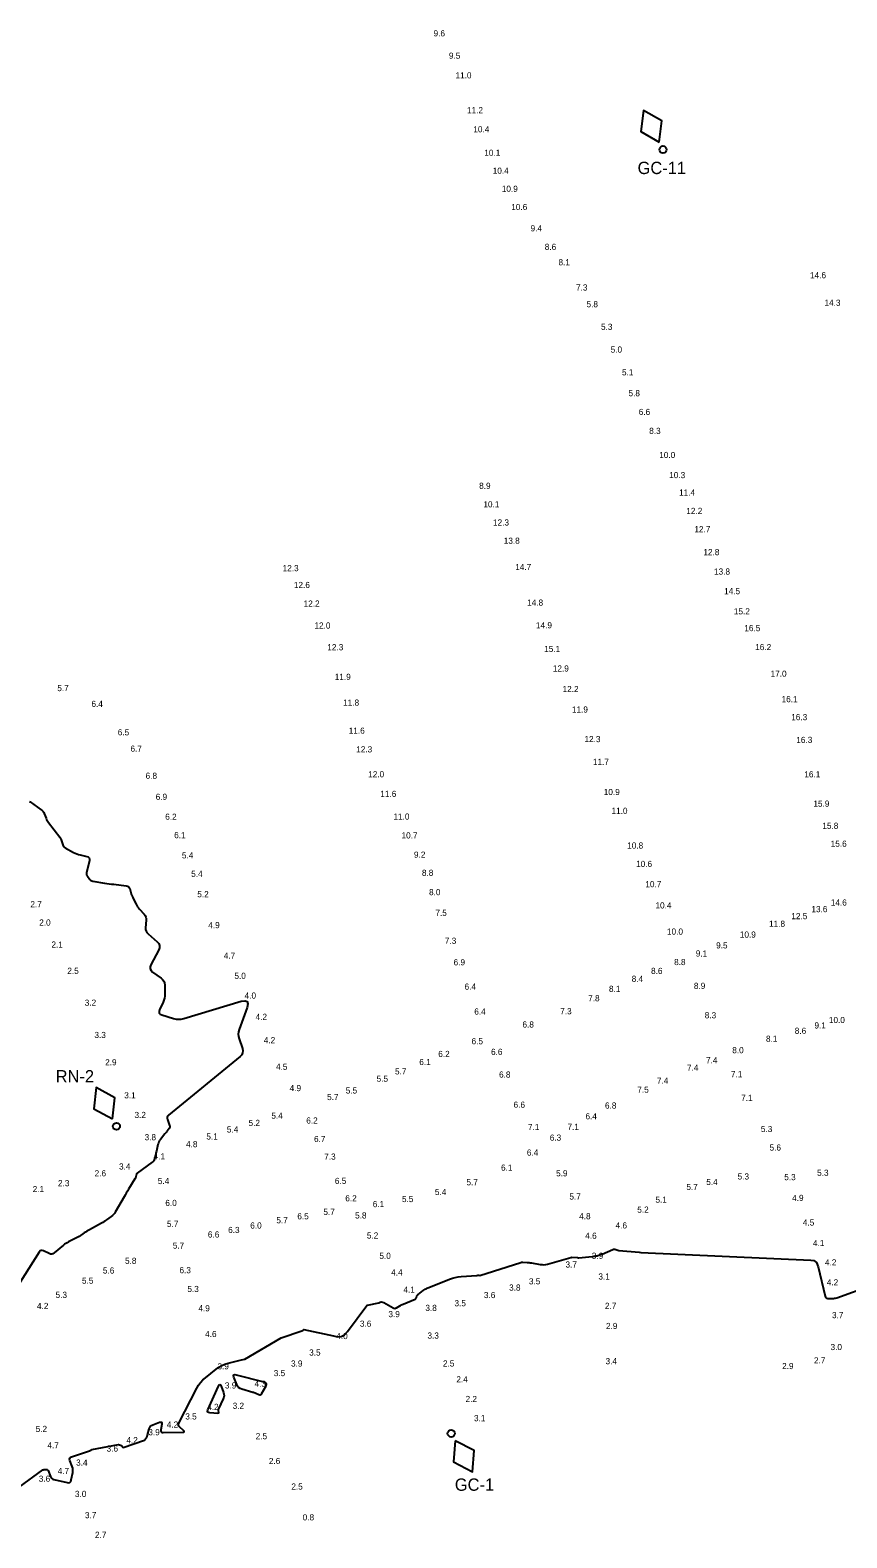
# Model space of a CAD drawing. Extents: x 837127 to 848654, y 3074248 to 3079868.
# Drawn here: x 847833 to 848248, y 3078565 to 3079331 of the extents above; entities that cross this region are included whole.
import ezdxf

# ---------------------------------------------------------------- set-up
doc = ezdxf.new("R2010")
doc.units = 0
for name, color, linetype in [('V-CHAN-NAID', 7, 'Continuous'), ('V-HYDS-MAJR', 7, 'Continuous'), ('V-HYDS-SOUN', 7, 'Continuous')]:
    doc.layers.add(name, color=color, linetype=linetype)

msp = doc.modelspace()

# ---------------------------------------------------------------- linework, layer by layer
at = {"layer": 'V-CHAN-NAID'}
for points in [[(848152.71, 3079274.19), (848154.07, 3079284.92), (848144.68, 3079290.3), (848143.32, 3079279.57)], [(847874.79, 3078777.98), (847875.89, 3078788.74), (847866.38, 3078793.9), (847865.28, 3078783.14)], [(848048.96, 3078614.55), (848048.07, 3078603.77), (848057.68, 3078598.8), (848058.57, 3078609.58)]]:
    msp.add_lwpolyline(points, close=True, dxfattribs=at)
for centre in [(848154.58, 3079270.43), (847876.75, 3078774.27), (848046.92, 3078618.22)]:
    msp.add_circle(centre, 1.8, dxfattribs=at)
at = {"layer": 'V-HYDS-MAJR'}
for points in [[(847832.64, 3078939.29), (847832.92, 3078939.06), (847838.55, 3078935.01), (847839.03, 3078934.61), (847839.44, 3078934.16), (847839.79, 3078933.65), (847840.06, 3078933.09), (847841, 3078930.73), (847841.26, 3078930.15), (847841.55, 3078929.59), (847841.88, 3078929.05), (847842.25, 3078928.54), (847847.95, 3078921.07), (847848.24, 3078920.65), (847848.5, 3078920.2), (847848.71, 3078919.73), (847848.88, 3078919.24), (847849.47, 3078917.23), (847849.65, 3078916.76), (847849.92, 3078916.35), (847850.26, 3078916), (847850.68, 3078915.72), (847855, 3078913.35), (847855.78, 3078912.96), (847856.59, 3078912.62), (847857.41, 3078912.34), (847858.26, 3078912.12), (847861.69, 3078911.33), (847862.41, 3078911.06), (847862.88, 3078910.61), (847863.08, 3078910), (847863.02, 3078909.23), (847861.62, 3078902.96), (847861.57, 3078902.5), (847861.61, 3078902.06), (847861.76, 3078901.64), (847862, 3078901.24), (847863.19, 3078899.7), (847863.51, 3078899.35), (847863.88, 3078899.08), (847864.29, 3078898.89), (847864.75, 3078898.77), (847870.73, 3078897.83), (847871.88, 3078897.65), (847873.04, 3078897.49), (847874.2, 3078897.33), (847875.36, 3078897.19), (847881.76, 3078896.44), (847882.37, 3078896.29), (847882.87, 3078896), (847883.25, 3078895.56), (847883.51, 3078894.99), (847884.31, 3078892.4), (847884.52, 3078891.76), (847884.76, 3078891.13), (847885.03, 3078890.51), (847885.32, 3078889.89), (847886.75, 3078887.05), (847887.11, 3078886.39), (847887.52, 3078885.76), (847887.96, 3078885.16), (847888.45, 3078884.58), (847890.84, 3078881.93), (847891.33, 3078881.28), (847891.66, 3078880.57), (847891.83, 3078879.81), (847891.85, 3078878.99), (847891.57, 3078875.14), (847891.6, 3078874.26), (847891.82, 3078873.45), (847892.23, 3078872.72), (847892.83, 3078872.07), (847897.5, 3078867.97), (847898.31, 3078867.04), (847898.7, 3078866.04), (847898.69, 3078864.96), (847898.27, 3078863.81), (847894.29, 3078856.24), (847893.91, 3078855.18), (847893.93, 3078854.22), (847894.35, 3078853.36), (847895.16, 3078852.58), (847899.44, 3078849.55), (847900.25, 3078848.83), (847900.82, 3078848.01), (847901.18, 3078847.06), (847901.3, 3078845.99), (847901.36, 3078841.38), (847901.31, 3078840.32), (847901.15, 3078839.29), (847900.88, 3078838.28), (847900.49, 3078837.29), (847898.7, 3078833.4), (847898.43, 3078832.51), (847898.54, 3078831.79), (847899.01, 3078831.23), (847899.85, 3078830.83), (847905.73, 3078829.03), (847907.06, 3078828.73), (847908.38, 3078828.63), (847909.7, 3078828.72), (847911.03, 3078829.02), (847940.24, 3078837.74), (847942.15, 3078838.05), (847943.28, 3078837.64), (847943.62, 3078836.49), (847943.19, 3078834.6), (847939.12, 3078823.47), (847938.79, 3078822.27), (847938.67, 3078821.06), (847938.77, 3078819.85), (847939.08, 3078818.64), (847940.78, 3078813.78), (847941.03, 3078812.62), (847940.92, 3078811.56), (847940.46, 3078810.59), (847939.64, 3078809.73), (847903.22, 3078779.91), (847902.78, 3078779.45), (847902.54, 3078778.93), (847902.49, 3078778.36), (847902.64, 3078777.74), (847903.81, 3078774.68), (847903.91, 3078774.28), (847903.91, 3078773.89), (847903.8, 3078773.51), (847903.59, 3078773.15), (847902.52, 3078771.74), (847902.25, 3078771.39), (847901.97, 3078771.04), (847901.7, 3078770.69), (847901.42, 3078770.35), (847899.16, 3078767.6), (847898.73, 3078767.01), (847898.38, 3078766.39), (847898.1, 3078765.72), (847897.89, 3078765.02), (847897.1, 3078761.66), (847896.99, 3078761.16), (847896.86, 3078760.66), (847896.74, 3078760.16), (847896.61, 3078759.66), (847896.09, 3078757.67), (847895.92, 3078757.19), (847895.69, 3078756.77), (847895.38, 3078756.39), (847895, 3078756.06), (847887.35, 3078750.39), (847887.16, 3078750.22), (847887, 3078750.03), (847886.89, 3078749.81), (847886.81, 3078749.56), (847886.56, 3078748.54), (847886.49, 3078748.28), (847886.4, 3078748.04), (847886.29, 3078747.8), (847886.17, 3078747.57), (847882.94, 3078742.24), (847882.36, 3078741.28), (847881.78, 3078740.31), (847881.21, 3078739.34), (847880.63, 3078738.37), (847876.12, 3078730.66), (847875.71, 3078730.04), (847875.25, 3078729.47), (847874.74, 3078728.94), (847874.16, 3078728.47), (847871.76, 3078726.68), (847871.16, 3078726.24), (847870.54, 3078725.83), (847869.9, 3078725.43), (847869.25, 3078725.06), (847863.12, 3078721.72), (847862.44, 3078721.33), (847861.76, 3078720.94), (847861.09, 3078720.52), (847860.42, 3078720.1), (847857.74, 3078718.35), (847857.1, 3078717.94), (847856.44, 3078717.55), (847855.78, 3078717.19), (847855.1, 3078716.84), (847852.36, 3078715.49), (847851.69, 3078715.13), (847851.05, 3078714.74), (847850.42, 3078714.31), (847849.83, 3078713.84), (847845.1, 3078709.9), (847844.49, 3078709.5), (847843.86, 3078709.32), (847843.2, 3078709.35), (847842.52, 3078709.6), (847839.74, 3078711), (847839.08, 3078711.22), (847838.49, 3078711.19), (847837.97, 3078710.91), (847837.52, 3078710.38), (847827.04, 3078693.68)], [(847827.34, 3078590.93), (847839.42, 3078599.71), (847839.63, 3078599.83), (847839.85, 3078599.92), (847840.08, 3078599.96), (847840.33, 3078599.96), (847841.32, 3078599.89), (847841.55, 3078599.84), (847841.74, 3078599.74), (847841.9, 3078599.59), (847842.01, 3078599.38), (847843.25, 3078596.3), (847843.54, 3078595.76), (847843.92, 3078595.34), (847844.4, 3078595.03), (847844.97, 3078594.82), (847851.69, 3078593.24), (847852.48, 3078593.17), (847853.1, 3078593.37), (847853.54, 3078593.85), (847853.81, 3078594.6), (847854.56, 3078598.32), (847854.67, 3078599.11), (847854.65, 3078599.89), (847854.52, 3078600.65), (847854.28, 3078601.41), (847853.07, 3078604.41), (847852.9, 3078605.1), (847853, 3078605.66), (847853.37, 3078606.1), (847854, 3078606.42), (847863.12, 3078609.39), (847863.43, 3078609.51), (847863.72, 3078609.67), (847863.99, 3078609.86), (847864.24, 3078610.08), (847877.79, 3078612.58), (847879.28, 3078612.03), (847880.17, 3078611.15), (847891.03, 3078614.84), (847891.56, 3078615.42), (847892, 3078616.05), (847892.34, 3078616.74), (847892.59, 3078617.49), (847893.4, 3078620.57), (847893.67, 3078621.28), (847894.08, 3078621.87), (847894.62, 3078622.33), (847895.3, 3078622.67), (847898.65, 3078623.91), (847899.24, 3078624.04), (847899.62, 3078623.93), (847899.81, 3078623.57), (847899.78, 3078622.97), (847899.28, 3078620.05), (847899.27, 3078619.42), (847899.47, 3078618.97), (847899.88, 3078618.7), (847900.51, 3078618.63), (847910.48, 3078618.84), (847910.98, 3078618.91), (847911.21, 3078619.08), (847911.15, 3078619.36), (847910.82, 3078619.74), (847908.92, 3078621.49), (847908.54, 3078621.95), (847908.36, 3078622.43), (847908.37, 3078622.96), (847908.56, 3078623.51), (847917.69, 3078641.25), (847918.56, 3078642.74), (847919.57, 3078644.12), (847920.72, 3078645.39), (847922.01, 3078646.55), (847927.44, 3078650.94), (847928.85, 3078651.95), (847930.33, 3078652.78), (847931.91, 3078653.45), (847933.56, 3078653.94), (847940.4, 3078655.55), (847942.11, 3078655.88), (847960.51, 3078666.83), (847970.92, 3078670.42), (847971.29, 3078670.57), (847971.63, 3078670.77), (847971.95, 3078671), (847987.04, 3078667.88), (847989.13, 3078667.36), (847991.02, 3078667.53), (847992.72, 3078668.39), (847994.22, 3078669.94), (848003.98, 3078683.15), (848004.16, 3078683.34), (848004.36, 3078683.43), (848010.1, 3078684.65), (848010.74, 3078684.95), (848011.39, 3078685.06), (848012.03, 3078684.98), (848012.68, 3078684.7), (848017.37, 3078682.02), (848017.8, 3078681.84), (848018.22, 3078681.78), (848018.65, 3078681.84), (848019.07, 3078682.03), (848020.76, 3078683.01), (848021.19, 3078683.25), (848021.62, 3078683.48), (848022.07, 3078683.69), (848022.51, 3078683.88), (848028.63, 3078686.43), (848028.84, 3078686.54), (848029.01, 3078686.69), (848029.14, 3078686.88), (848029.23, 3078687.11), (848029.51, 3078688.08), (848029.6, 3078688.31), (848029.72, 3078688.52), (848029.87, 3078688.7), (848030.05, 3078688.86), (848032.64, 3078690.78), (848033.15, 3078691.13), (848033.68, 3078691.45), (848034.22, 3078691.73), (848034.79, 3078691.98), (848046.12, 3078696.56), (848047.53, 3078697.07), (848048.97, 3078697.47), (848050.43, 3078697.75), (848051.92, 3078697.92), (848059.95, 3078698.53), (848060.44, 3078698.56), (848060.92, 3078698.55), (848061.41, 3078698.5), (848082.29, 3078705.13), (848082.74, 3078705.29), (848083.26, 3078705.31), (848085.48, 3078705.15), (848086.03, 3078705.1), (848086.58, 3078705.04), (848087.13, 3078704.96), (848087.68, 3078704.87), (848092.18, 3078704.08), (848093.11, 3078703.97), (848094.03, 3078703.96), (848094.95, 3078704.06), (848095.87, 3078704.26), (848107.72, 3078707.53), (848107.97, 3078707.62), (848108.21, 3078707.74), (848111.12, 3078707.63), (848111.34, 3078707.5), (848111.59, 3078707.44), (848111.87, 3078707.43), (848120.28, 3078708.33), (848120.57, 3078708.37), (848120.85, 3078708.43), (848121.13, 3078708.5), (848121.41, 3078708.58), (848122.51, 3078708.96), (848122.79, 3078709.05), (848123.06, 3078709.15), (848123.33, 3078709.26), (848123.6, 3078709.37), (848129.02, 3078711.66), (848129.4, 3078711.78), (848129.79, 3078711.84), (848130.18, 3078711.82), (848130.58, 3078711.73), (848132.16, 3078711.22), (848142.5, 3078710.32), (848143.24, 3078710.12), (848229.64, 3078706.17), (848231.31, 3078706.1), (848232.57, 3078704.99), (848233.42, 3078702.85), (848236.99, 3078687.99), (848237.17, 3078687.5), (848237.47, 3078687.15), (848237.88, 3078686.93), (848238.39, 3078686.85), (848240.67, 3078686.8), (848241.23, 3078686.81), (848241.79, 3078686.87), (848242.34, 3078686.99), (848242.88, 3078687.16), (848260.67, 3078693.63)]]:
    msp.add_lwpolyline(points, dxfattribs=at)
for points in [[(847929.29, 3078643.11), (847929.62, 3078642.9), (847929.94, 3078642.29), (847931.2, 3078639.05), (847931.42, 3078638.25), (847931.48, 3078637.45), (847931.36, 3078636.65), (847931.07, 3078635.87), (847928.6, 3078630.7), (847928.52, 3078630.48), (847928.47, 3078630.26), (847928.46, 3078630.04), (847928.48, 3078629.81), (847928.64, 3078628.88), (847928.64, 3078628.67), (847928.58, 3078628.53), (847928.44, 3078628.45), (847928.24, 3078628.44), (847924.16, 3078628.69), (847923.53, 3078628.81), (847923.17, 3078629.1), (847923.08, 3078629.56), (847923.25, 3078630.17), (847928.61, 3078642.32), (847928.96, 3078642.92)], [(847949.89, 3078637.75), (847949.57, 3078637.72), (847949.2, 3078637.83), (847947.63, 3078638.52), (847947.24, 3078638.69), (847946.84, 3078638.84), (847946.43, 3078638.98), (847946.02, 3078639.11), (847940.47, 3078640.73), (847939.6, 3078641.09), (847938.88, 3078641.6), (847938.31, 3078642.27), (847937.89, 3078643.1), (847936.47, 3078646.75), (847936.28, 3078647.52), (847936.41, 3078647.99), (847936.87, 3078648.18), (847937.66, 3078648.08), (847951.77, 3078644.42), (847952.49, 3078644.11), (847952.88, 3078643.66), (847952.94, 3078643.07), (847952.66, 3078642.33), (847950.4, 3078638.23), (847950.17, 3078637.92)]]:
    msp.add_lwpolyline(points, close=True, dxfattribs=at)

# ---------------------------------------------------------------- texts
at = {"layer": 'V-CHAN-NAID'}
for s, p in [('GC-11', (848141.67, 3079257.96)), ('RN-2', (847845.88, 3078796.54)), ('GC-1', (848048.76, 3078589.11))]:
    msp.add_text(s, height=6.25, dxfattribs=at).set_placement(p)
at = {"layer": 'V-HYDS-SOUN'}
for s, p in [('9.6', (848037.95, 3079327.89)), ('9.5', (848045.77, 3079316.53)), ('11.0 ', (848049.11, 3079306.55)), ('11.2 ', (848054.96, 3079288.87)), ('10.4 ', (848058.19, 3079279.16)), ('10.1 ', (848063.74, 3079267.23)), ('10.4 ', (848068.03, 3079258.1)), ('10.9 ', (848072.64, 3079248.91)), ('10.6 ', (848077.45, 3079239.66)), ('9.4', (848087.26, 3079228.84)), ('8.6', (848094.48, 3079219.42)), ('8.1', (848101.46, 3079211.61)), ('14.6 ', (848229.31, 3079205.03)), ('7.3', (848110.38, 3079198.79)), ('5.8', (848115.71, 3079190.3)), ('14.3 ', (848236.66, 3079191.03)), ('5.3', (848123.07, 3079178.81)), ('5.0', (848127.96, 3079167.27)), ('5.1', (848133.73, 3079155.71)), ('5.8', (848137.05, 3079145.11)), ('6.6', (848142.26, 3079135.57)), ('8.3', (848147.57, 3079125.96)), ('10.0 ', (848152.66, 3079113.7)), ('8.9', (848061.14, 3079098.06)), ('10.3 ', (848157.73, 3079103.49)), ('11.4 ', (848162.74, 3079094.65)), ('10.1 ', (848063.29, 3079088.64)), ('12.2 ', (848166.43, 3079085.29)), ('12.3 ', (848068.16, 3079079.42)), ('12.7 ', (848170.53, 3079076.01)), ('13.8 ', (848073.63, 3079070.15)), ('12.8 ', (848175.12, 3079064.36)), ('12.3 ', (847961.24, 3079056.24)), ('14.7 ', (848079.48, 3079056.79)), ('13.8 ', (848180.51, 3079054.5)), ('12.6 ', (847966.97, 3079047.67)), ('14.5 ', (848185.63, 3079044.54)), ('12.2 ', (847971.91, 3079038.22)), ('14.8 ', (848085.51, 3079038.72)), ('15.2 ', (848190.59, 3079034.28)), ('12.0 ', (847977.41, 3079027.08)), ('14.9 ', (848090.01, 3079027.21)), ('16.5 ', (848195.92, 3079025.76)), ('12.3 ', (847983.95, 3079016.08)), ('15.1 ', (848094.16, 3079015.18)), ('16.2 ', (848201.44, 3079016.13)), ('11.9 ', (847987.73, 3079001)), ('12.9 ', (848098.58, 3079005.25)), ('17.0 ', (848209.27, 3079002.6)), ('5.7', (847846.72, 3078995.3)), ('12.2 ', (848103.53, 3078994.82)), ('6.4', (847864.06, 3078987.29)), ('11.8 ', (847991.98, 3078987.92)), ('11.9 ', (848108.29, 3078984.4)), ('16.1 ', (848214.86, 3078989.68)), ('16.3 ', (848219.75, 3078980.55)), ('6.5', (847877.44, 3078972.84)), ('11.6 ', (847994.84, 3078973.66)), ('12.3 ', (848114.66, 3078969.39)), ('16.3 ', (848222.34, 3078968.96)), ('6.7', (847883.89, 3078964.53)), ('12.3 ', (847998.63, 3078964.17)), ('11.7 ', (848118.95, 3078957.8)), ('6.8', (847891.6, 3078950.76)), ('12.0 ', (848004.72, 3078951.51)), ('16.1 ', (848226.42, 3078951.51)), ('6.9', (847896.71, 3078940.07)), ('11.6 ', (848010.89, 3078941.57)), ('10.9 ', (848124.47, 3078942.5)), ('15.9 ', (848231.02, 3078936.6)), ('6.2', (847901.56, 3078929.94)), ('11.0 ', (848017.57, 3078930.02)), ('11.0 ', (848128.41, 3078932.97)), ('15.8 ', (848235.58, 3078925.35)), ('6.1', (847906.11, 3078920.6)), ('10.7 ', (848021.67, 3078920.45)), ('10.8 ', (848136.37, 3078915.32)), ('15.6 ', (848239.81, 3078916.25)), ('5.4', (847910.04, 3078910.34)), ('9.2', (848028, 3078910.67)), ('10.6 ', (848140.91, 3078905.98)), ('5.4', (847914.77, 3078900.96)), ('8.8', (848032.05, 3078901.46)), ('5.2', (847917.86, 3078890.58)), ('8.0', (848035.67, 3078891.65)), ('10.7 ', (848145.62, 3078895.72)), ('2.7', (847833.03, 3078885.51)), ('10.4 ', (848150.76, 3078884.91)), ('13.6 ', (848230.02, 3078883.02)), ('14.6 ', (848239.87, 3078886.37)), ('2.0', (847837.51, 3078876.2)), ('7.5', (848038.89, 3078881.11)), ('11.8 ', (848208.48, 3078875.58)), ('12.5 ', (848219.81, 3078879.47)), ('4.9', (847923.44, 3078874.89)), ('10.0 ', (848156.61, 3078871.61)), ('10.9 ', (848193.63, 3078870.09)), ('2.1', (847843.73, 3078865)), ('7.3', (848043.69, 3078866.95)), ('9.1', (848171.25, 3078860.48)), ('9.5', (848181.58, 3078864.6)), ('4.7', (847931.34, 3078859.4)), ('6.9', (848048.14, 3078856.02)), ('8.8', (848160.23, 3078856.14)), ('2.5', (847851.81, 3078851.69)), ('5.0', (847936.73, 3078849.14)), ('8.4', (848138.68, 3078847.62)), ('8.6', (848148.52, 3078851.64)), ('4.0', (847941.91, 3078839.11)), ('6.4', (848053.72, 3078843.67)), ('7.8', (848116.55, 3078837.73)), ('8.1', (848127.11, 3078842.52)), ('8.9', (848170.28, 3078844.02)), ('3.2', (847860.65, 3078835.49)), ('6.4', (848058.66, 3078831)), ('7.3', (848102.34, 3078831.15)), ('4.2', (847947.51, 3078828.31)), ('6.8', (848083.14, 3078824.42)), ('8.3', (848175.8, 3078829.1)), ('9.1', (848231.56, 3078823.94)), ('10.0 ', (848238.9, 3078826.69)), ('3.3', (847865.57, 3078819.08)), ('4.2', (847951.66, 3078816.45)), ('6.5', (848057.28, 3078815.93)), ('8.1', (848206.92, 3078817.18)), ('8.6', (848221.56, 3078821.21)), ('6.2', (848040.35, 3078809.44)), ('6.6', (848067.18, 3078810.52)), ('8.0', (848189.77, 3078811.37)), ('2.9', (847871.03, 3078805.22)), ('4.5', (847957.86, 3078802.94)), ('5.7', (848018.35, 3078800.59)), ('6.1', (848030.71, 3078805.35)), ('6.8', (848071.25, 3078798.97)), ('7.4', (848166.77, 3078802.47)), ('7.4', (848176.45, 3078806.29)), ('7.1', (848189.1, 3078799.21)), ('4.9', (847964.8, 3078792.11)), ('5.5', (848009, 3078796.89)), ('7.5', (848141.53, 3078791.3)), ('7.4', (848151.49, 3078795.85)), ('3.1', (847880.73, 3078788.44)), ('5.7', (847983.84, 3078787.56)), ('5.5', (847993.31, 3078790.91)), ('6.6', (848078.63, 3078783.67)), ('7.1', (848194.3, 3078787.16)), ('3.2', (847885.95, 3078778.45)), ('5.4', (847955.51, 3078778.1)), ('6.4', (848115.16, 3078777.79)), ('6.8', (848125.09, 3078783.25)), ('5.4', (847932.89, 3078771.1)), ('5.2', (847943.92, 3078774.41)), ('6.2', (847973.26, 3078775.64)), ('7.1', (848085.96, 3078772.32)), ('7.1', (848106.04, 3078772.42)), ('5.3', (848204.33, 3078771.32)), ('3.8', (847891.07, 3078767.17)), ('4.8', (847912.15, 3078763.62)), ('5.1', (847922.47, 3078767.54)), ('6.7', (847977.2, 3078766.23)), ('6.3', (848097.03, 3078766.94)), ('5.6', (848208.74, 3078761.9)), ('4.1', (847895.67, 3078757.4)), ('7.3', (847982.38, 3078757.3)), ('6.4', (848085.39, 3078759.37)), ('2.6', (847865.67, 3078748.82)), ('3.4', (847878.08, 3078752.3)), ('6.1', (848072.26, 3078751.7)), ('5.9', (848100.25, 3078748.82)), ('5.3', (848192.5, 3078747.23)), ('5.3', (848216.21, 3078746.88)), ('5.3', (848232.93, 3078749.11)), ('2.1', (847834.19, 3078740.8)), ('2.3', (847847.05, 3078743.82)), ('5.4', (847897.81, 3078744.89)), ('6.5', (847987.8, 3078744.96)), ('5.4', (848038.63, 3078739.31)), ('5.7', (848054.68, 3078744.28)), ('5.7', (848166.47, 3078741.88)), ('5.4', (848176.58, 3078744.43)), ('6.0', (847901.61, 3078733.77)), ('6.2', (847993.09, 3078736.12)), ('6.1', (848007.06, 3078733.18)), ('5.5', (848021.9, 3078735.74)), ('5.7', (848107, 3078737.04)), ('5.2', (848141.49, 3078730.37)), ('5.1', (848150.74, 3078735.43)), ('4.9', (848220.23, 3078736.31)), ('5.7', (847902.43, 3078723.11)), ('6.0', (847944.78, 3078722.31)), ('5.7', (847958.06, 3078724.98)), ('6.5', (847968.71, 3078726.98)), ('5.7', (847981.95, 3078729.21)), ('5.8', (847998.07, 3078727.43)), ('4.8', (848111.97, 3078727.03)), ('4.6', (848130.47, 3078722.36)), ('4.5', (848225.65, 3078723.84)), ('6.6', (847923.25, 3078717.75)), ('6.3', (847933.55, 3078720.03)), ('5.2', (848004.07, 3078717.23)), ('4.6', (848115.04, 3078717.12)), ('5.7', (847905.4, 3078712.1)), ('5.0', (848010.42, 3078706.9)), ('3.9', (848118.4, 3078706.94)), ('4.1', (848230.79, 3078713.38)), ('5.6', (847869.88, 3078699.45)), ('5.8', (847881.12, 3078704.36)), ('6.3', (847908.81, 3078699.62)), ('3.7', (848105.02, 3078702.5)), ('4.2', (848236.9, 3078703.55)), ('5.5', (847859.24, 3078694.3)), ('4.4', (848016.39, 3078698.46)), ('3.5', (848086.42, 3078693.96)), ('3.1', (848121.73, 3078696.41)), ('4.2', (848237.82, 3078693.42)), ('5.3', (847845.83, 3078687.07)), ('5.3', (847912.82, 3078690.05)), ('4.1', (848022.64, 3078689.71)), ('3.6', (848063.53, 3078686.98)), ('3.8', (848076.36, 3078690.77)), ('4.2', (847836.37, 3078681.43)), ('4.9', (847918.42, 3078680.27)), ('3.9', (848015.01, 3078677.3)), ('3.8', (848033.8, 3078680.44)), ('3.5', (848048.59, 3078682.83)), ('2.7', (848125.07, 3078681.5)), ('3.7', (848240.48, 3078676.79)), ('3.6', (848000.51, 3078672.43)), ('2.9', (848125.59, 3078671.26)), ('4.6', (847921.85, 3078667.18)), ('4.0', (847988.49, 3078666.15)), ('3.3', (848034.86, 3078666.39)), ('3.5', (847974.73, 3078657.78)), ('3.4', (848125.37, 3078653.39)), ('2.7', (848231.32, 3078653.81)), ('3.0', (848239.74, 3078660.57)), ('3.9', (847928.12, 3078650.79)), ('3.5', (847956.73, 3078647.34)), ('3.9', (847965.51, 3078652.2)), ('2.5', (848042.74, 3078652.23)), ('2.9', (848215.13, 3078650.92)), ('3.9', (847931.89, 3078641.07)), ('4.3', (847946.95, 3078641.92)), ('2.4', (848049.55, 3078644.18)), ('4.2', (847922.89, 3078630.16)), ('3.2', (847935.84, 3078630.72)), ('2.2', (848054.22, 3078634.17)), ('3.5', (847911.76, 3078625.33)), ('3.1', (848058.5, 3078624.46)), ('5.2', (847835.7, 3078618.96)), ('3.9', (847892.97, 3078617.3)), ('4.2', (847902.36, 3078621.18)), ('2.5', (847947.55, 3078615.28)), ('4.7', (847841.68, 3078610.64)), ('3.6', (847871.77, 3078609.01)), ('4.2', (847881.81, 3078613.23)), ('3.4', (847856.27, 3078601.86)), ('2.6', (847954.23, 3078602.67)), ('3.6', (847837.3, 3078593.68)), ('4.7', (847846.92, 3078597.63)), ('3.0', (847855.66, 3078585.96)), ('2.5', (847965.67, 3078589.71)), ('3.7', (847860.75, 3078575.19)), ('0.8', (847971.43, 3078574.07)), ('2.7', (847865.87, 3078565.2))]:
    msp.add_text(s, height=3.125, dxfattribs=at).set_placement(p)

doc.saveas('drawing.dxf')
